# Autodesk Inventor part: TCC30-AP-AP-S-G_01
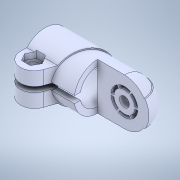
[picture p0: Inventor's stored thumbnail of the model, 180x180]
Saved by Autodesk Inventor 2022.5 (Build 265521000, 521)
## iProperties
Created: 2023-09
Part Number: TCC30-AP-AP-S-G_01
Material: 一般
Document SubType Name: Modeling
Designer: ImaoCorp
Density: 1 g/cm^3
Appearance: 既定
Author: ImaoCorp
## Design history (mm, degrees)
feature "TCC30-AP-AP-S-G_01"
node "ソリッド1"
